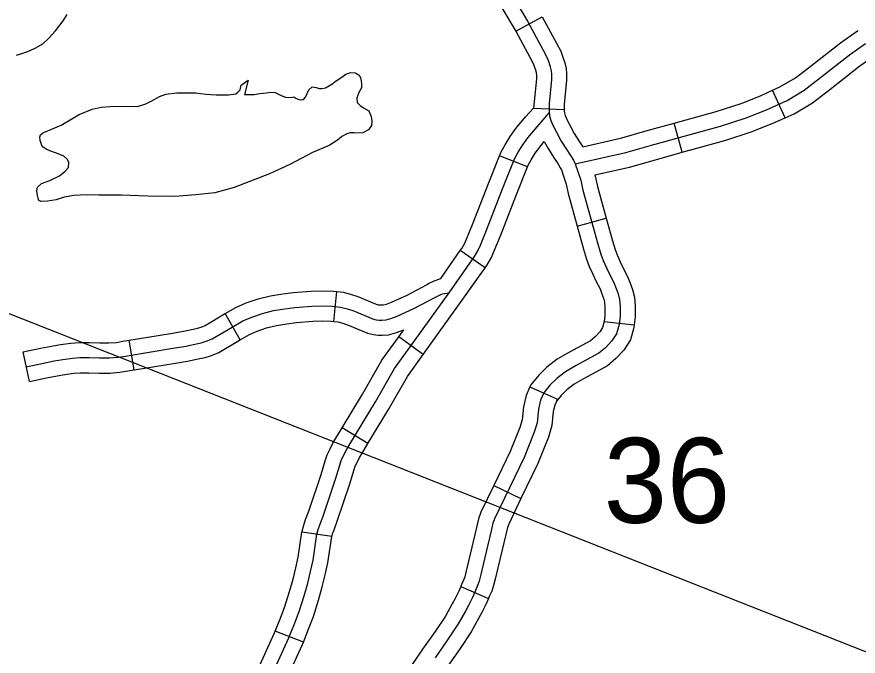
# Model space of a CAD drawing. Extents: x -3711 to 825, y -151 to 1050.
# Drawn here: x -2656.41 to -2609.55, y 277.96 to 313.59 of the extents above; entities that cross this region are included whole.
import ezdxf

# ---------------------------------------------------------------- set-up
doc = ezdxf.new("R2010")
doc.units = 0
for name, color, linetype in [('Level 32', 7, 'Continuous'), ('Level 35', 7, 'Continuous'), ('Level 5', 7, 'Continuous'), ('R_Dimension', 7, 'Continuous')]:
    doc.layers.add(name, color=color, linetype=linetype)

msp = doc.modelspace()

# ---------------------------------------------------------------- linework, layer by layer
at = {"layer": 'Level 32'}
for p, q in [((-2628.618, 312.787), (-2627.143, 313.594)), ((-2613.618, 307.967), (-2614.316, 309.497)), ((-2627.637, 308.51), (-2625.926, 308.429)), ((-2619.345, 306.045), (-2619.794, 307.665)), ((-2627.959, 305.224), (-2629.519, 305.85)), ((-2625.202, 301.927), (-2623.581, 302.374)), ((-2630.333, 299.602), (-2631.708, 300.57)), ((-2638.759, 296.615), (-2638.58, 298.287)), ((-2643.97, 295.593), (-2644.804, 297.053)), ((-2623.689, 296.614), (-2622.018, 296.428)), ((-2633.77, 294.775), (-2635.136, 295.756)), ((-2649.881, 293.91), (-2650.156, 295.569)), ((-2655.706, 293.269), (-2656.053, 294.915)), ((-2627.829, 292.973), (-2626.298, 292.278)), ((-2636.854, 289.808), (-2638.293, 290.678)), ((-2629.843, 287.474), (-2628.329, 286.743)), ((-2638.862, 284.622), (-2640.526, 284.867)), ((-2631.682, 281.844), (-2630.14, 281.174)), ((-2640.449, 278.744), (-2642.015, 279.357))]:
    msp.add_line(p, q, dxfattribs=at)
for points in [[(-2630.523, 318.676), (-2630.523, 318.262), (-2630.505, 317.663), (-2630.469, 316.962), (-2630.411, 316.498), (-2630.332, 316.081), (-2630.231, 315.716), (-2630.063, 315.233), (-2629.745, 314.657), (-2629.331, 314.001), (-2628.701, 312.938), (-2628.618, 312.787)], [(-2628.614, 314.44), (-2627.97, 313.355), (-2627.089, 311.743), (-2626.885, 311.336), (-2626.784, 311.064), (-2626.699, 310.81), (-2626.648, 310.589), (-2626.631, 310.386), (-2626.631, 310.097), (-2626.767, 308.757), (-2626.767, 308.401), (-2626.756, 308.241), (-2626.733, 308.079), (-2626.665, 307.807), (-2626.546, 307.553), (-2626.36, 307.163), (-2626.089, 306.671), (-2625.817, 306.23), (-2625.58, 305.873), (-2625.411, 305.602), (-2625.303, 305.395), (-2625.156, 304.974), (-2625.004, 304.482), (-2624.885, 303.94), (-2624.037, 300.869), (-2623.885, 300.36), (-2623.749, 300.004), (-2623.563, 299.597), (-2623.408, 299.25), (-2623.154, 298.779), (-2623.03, 298.452), (-2622.922, 298.156), (-2622.843, 297.831), (-2622.81, 297.456), (-2622.81, 296.912), (-2622.863, 296.439), (-2623.009, 295.933), (-2623.263, 295.535), (-2623.625, 295.154), (-2623.987, 294.846), (-2625.255, 294.157), (-2625.843, 293.815), (-2626.337, 293.436), (-2626.716, 293.056), (-2627.057, 292.638), (-2627.247, 292.221), (-2627.361, 291.727), (-2627.437, 290.968), (-2627.589, 290.436), (-2628.158, 289.031), (-2629.789, 285.652)], [(-2627.143, 313.594), (-2626.344, 312.133), (-2626.114, 311.672), (-2625.991, 311.345), (-2625.889, 311.038), (-2625.815, 310.719), (-2625.79, 310.421), (-2625.79, 310.055), (-2625.926, 308.715), (-2625.926, 308.429), (-2625.919, 308.329), (-2625.907, 308.241), (-2625.869, 308.089), (-2625.807, 307.956)], [(-2628.618, 312.787), (-2627.834, 311.353), (-2627.657, 311), (-2627.576, 310.784), (-2627.509, 310.582), (-2627.481, 310.459), (-2627.472, 310.351), (-2627.472, 310.14), (-2627.637, 308.51)], [(-2614.316, 309.497), (-2613.904, 309.685), (-2613.038, 310.201), (-2612.155, 310.874), (-2610.531, 312.153), (-2609.596, 312.812), (-2609.549, 312.839)], [(-2625.303, 305.395), (-2622.496, 306.037), (-2621.066, 306.44), (-2617.219, 307.508), (-2615.789, 307.972), (-2614.661, 308.415), (-2613.513, 308.939), (-2612.566, 309.504), (-2611.64, 310.209), (-2610.028, 311.479), (-2609.142, 312.104)], [(-2613.618, 307.967), (-2613.122, 308.194), (-2612.095, 308.806), (-2611.125, 309.545), (-2609.526, 310.805), (-2608.688, 311.395), (-2608.706, 311.385)], [(-2619.794, 307.665), (-2617.461, 308.313), (-2616.073, 308.763), (-2614.99, 309.189), (-2614.316, 309.497)], [(-2629.519, 305.85), (-2629.433, 306.064), (-2629.219, 306.466), (-2628.932, 306.928), (-2628.615, 307.373), (-2628.071, 308.011), (-2627.637, 308.51)], [(-2642.298, 276.691), (-2641.275, 278.939), (-2640.95, 279.771), (-2640.68, 280.457), (-2640.41, 281.323), (-2640.208, 282.031), (-2640.051, 282.683), (-2639.905, 283.313), (-2639.691, 284.763), (-2639.624, 285.022), (-2639.532, 285.288), (-2639.354, 285.764), (-2638.658, 287.821), (-2638.422, 288.608), (-2638.343, 288.867), (-2638.208, 289.137), (-2638.062, 289.429), (-2637.916, 289.676), (-2636.433, 292.127), (-2635.366, 293.994), (-2632.338, 298.213), (-2630.917, 300.233), (-2630.726, 300.56), (-2630.591, 300.874), (-2630.254, 301.706), (-2629.356, 304), (-2628.67, 305.709), (-2628.49, 306.046), (-2628.232, 306.462), (-2627.951, 306.856), (-2627.434, 307.463), (-2626.756, 308.241)], [(-2625.807, 307.956), (-2625.786, 307.912), (-2625.612, 307.547), (-2625.362, 307.094), (-2625.109, 306.683), (-2624.889, 306.352)], [(-2619.345, 306.045), (-2616.977, 306.703), (-2615.505, 307.18), (-2614.332, 307.641), (-2613.618, 307.967)], [(-2624.889, 306.352), (-2622.704, 306.851), (-2621.293, 307.249), (-2619.794, 307.665)], [(-2627.959, 305.224), (-2627.907, 305.354), (-2627.762, 305.626), (-2627.532, 305.996), (-2627.288, 306.338), (-2627.031, 306.639)], [(-2627.031, 306.639), (-2626.815, 306.247), (-2626.525, 305.776), (-2626.286, 305.418), (-2626.141, 305.184), (-2626.076, 305.061), (-2625.955, 304.712), (-2625.817, 304.268), (-2625.701, 303.738), (-2625.202, 301.927)], [(-2624.209, 304.783), (-2622.288, 305.222), (-2620.84, 305.63), (-2619.345, 306.045)], [(-2631.708, 300.57), (-2631.625, 300.689), (-2631.478, 300.939), (-2631.367, 301.198), (-2631.035, 302.017), (-2630.137, 304.31), (-2629.519, 305.85)], [(-2630.333, 299.602), (-2630.209, 299.778), (-2629.974, 300.18), (-2629.815, 300.551), (-2629.473, 301.395), (-2628.574, 303.69), (-2627.959, 305.224)], [(-2624.209, 304.783), (-2624.069, 304.141), (-2623.581, 302.374)], [(-2623.581, 302.374), (-2623.23, 301.102), (-2623.088, 300.631), (-2622.974, 300.329), (-2622.797, 299.943), (-2622.653, 299.621), (-2622.388, 299.129), (-2622.243, 298.746), (-2622.116, 298.401), (-2622.011, 297.967), (-2621.97, 297.492), (-2621.97, 296.866), (-2622.018, 296.428)], [(-2625.202, 301.927), (-2624.845, 300.637), (-2624.681, 300.09), (-2624.525, 299.679), (-2624.329, 299.25), (-2624.163, 298.879), (-2623.921, 298.429), (-2623.818, 298.159), (-2623.728, 297.912), (-2623.675, 297.694), (-2623.651, 297.419), (-2623.651, 296.959), (-2623.689, 296.614)], [(-2632.802, 299.015), (-2631.708, 300.57)], [(-2633.77, 294.775), (-2631.653, 297.726), (-2630.333, 299.602)], [(-2633.556, 298.683), (-2633.481, 298.723), (-2633.169, 298.879), (-2632.802, 299.015)], [(-2638.58, 298.287), (-2638.22, 298.248), (-2637.762, 298.123), (-2637.407, 298.005), (-2636.484, 297.621), (-2636.34, 297.561), (-2636.258, 297.54), (-2636.191, 297.534), (-2636.112, 297.534), (-2635.978, 297.543), (-2635.828, 297.581), (-2635.545, 297.689), (-2634.665, 298.089), (-2633.556, 298.683)], [(-2655.879, 294.092), (-2654.917, 294.295), (-2654.326, 294.413), (-2653.854, 294.497), (-2653.314, 294.565), (-2652.892, 294.599), (-2652.386, 294.599), (-2651.795, 294.582), (-2651.255, 294.582), (-2650.765, 294.616), (-2650.36, 294.683), (-2647.71, 295.122), (-2646.968, 295.241), (-2646.58, 295.325), (-2646.141, 295.426), (-2645.854, 295.511), (-2645.533, 295.646), (-2644.419, 296.305), (-2643.828, 296.642), (-2643.322, 296.862), (-2642.731, 297.065), (-2642.107, 297.217), (-2641.482, 297.318), (-2640.925, 297.386), (-2639.98, 297.47), (-2639.373, 297.487), (-2638.849, 297.47), (-2638.377, 297.419), (-2638.006, 297.318), (-2637.702, 297.217), (-2636.807, 296.845), (-2636.605, 296.761), (-2636.402, 296.71), (-2636.233, 296.693), (-2636.082, 296.693), (-2635.845, 296.71), (-2635.575, 296.778), (-2635.221, 296.913), (-2634.292, 297.335), (-2633.094, 297.977), (-2632.834, 298.107), (-2632.706, 298.154), (-2632.588, 298.182), (-2632.46, 298.201), (-2632.338, 298.213)], [(-2644.804, 297.053), (-2644.205, 297.395), (-2643.626, 297.646), (-2642.968, 297.872), (-2642.274, 298.041), (-2641.6, 298.151), (-2641.014, 298.222), (-2640.029, 298.31), (-2639.371, 298.328), (-2638.791, 298.309), (-2638.58, 298.287)], [(-2650.156, 295.569), (-2647.845, 295.952), (-2647.123, 296.067), (-2646.763, 296.145), (-2646.354, 296.24), (-2646.137, 296.304), (-2645.912, 296.398), (-2644.842, 297.031), (-2644.804, 297.053)], [(-2643.97, 295.593), (-2643.451, 295.89), (-2643.018, 296.078), (-2642.495, 296.257), (-2641.94, 296.392), (-2641.364, 296.486), (-2640.837, 296.55), (-2639.931, 296.631), (-2639.375, 296.646), (-2638.908, 296.631), (-2638.759, 296.615)], [(-2638.759, 296.615), (-2638.533, 296.591), (-2638.249, 296.513), (-2637.996, 296.429), (-2637.13, 296.069), (-2636.87, 295.961), (-2636.547, 295.88), (-2636.275, 295.853), (-2636.052, 295.853), (-2635.712, 295.877), (-2635.323, 295.974), (-2634.85, 296.154)], [(-2635.136, 295.756), (-2634.85, 296.154)], [(-2623.689, 296.614), (-2623.69, 296.604), (-2623.783, 296.283), (-2623.928, 296.055), (-2624.204, 295.766), (-2624.466, 295.543), (-2625.667, 294.89), (-2626.313, 294.515), (-2626.893, 294.069), (-2627.34, 293.621), (-2627.777, 293.086), (-2627.828, 292.974)], [(-2622.018, 296.428), (-2622.035, 296.275), (-2622.236, 295.584), (-2622.598, 295.014), (-2623.047, 294.542), (-2623.509, 294.149), (-2624.843, 293.424), (-2625.374, 293.116), (-2625.781, 292.803), (-2626.092, 292.492), (-2626.337, 292.191), (-2626.298, 292.278)], [(-2638.293, 290.678), (-2637.158, 292.554), (-2636.074, 294.449), (-2635.136, 295.756)], [(-2656.053, 294.915), (-2655.086, 295.118), (-2654.483, 295.239), (-2653.98, 295.329), (-2653.4, 295.401), (-2652.925, 295.439), (-2652.373, 295.439), (-2651.783, 295.422), (-2651.284, 295.422), (-2650.864, 295.451), (-2650.498, 295.512), (-2650.156, 295.569)], [(-2649.881, 293.91), (-2647.576, 294.293), (-2646.812, 294.414), (-2646.396, 294.505), (-2645.927, 294.613), (-2645.571, 294.718), (-2645.154, 294.893), (-2643.997, 295.578), (-2643.97, 295.593)], [(-2636.854, 289.808), (-2635.709, 291.701), (-2634.658, 293.539), (-2633.77, 294.775)], [(-2655.706, 293.269), (-2654.748, 293.471), (-2654.17, 293.587), (-2653.728, 293.666), (-2653.228, 293.729), (-2652.858, 293.758), (-2652.398, 293.758), (-2651.807, 293.741), (-2651.226, 293.741), (-2650.667, 293.78), (-2650.222, 293.854), (-2649.881, 293.91)], [(-2627.829, 292.973), (-2628.047, 292.492), (-2628.192, 291.864), (-2628.266, 291.126), (-2628.385, 290.71), (-2628.927, 289.372), (-2629.843, 287.474)], [(-2626.298, 292.278), (-2626.447, 291.95), (-2626.53, 291.59), (-2626.608, 290.809), (-2626.793, 290.162), (-2627.389, 288.691), (-2628.329, 286.743)], [(-2640.526, 284.867), (-2640.516, 284.931), (-2640.429, 285.266), (-2640.323, 285.572), (-2640.146, 286.046), (-2639.459, 288.077), (-2639.227, 288.851), (-2639.127, 289.179), (-2638.96, 289.512), (-2638.801, 289.831), (-2638.638, 290.108), (-2638.293, 290.678)], [(-2638.866, 284.596), (-2638.819, 284.778), (-2638.741, 285.003), (-2638.562, 285.482), (-2637.857, 287.566), (-2637.617, 288.365), (-2637.56, 288.555), (-2637.456, 288.761), (-2637.323, 289.027), (-2637.195, 289.245), (-2636.854, 289.808)], [(-2629.843, 287.474), (-2630.564, 285.981), (-2630.699, 285.614), (-2630.813, 285.138), (-2631.258, 283.253), (-2631.374, 282.721), (-2631.465, 282.389), (-2631.531, 282.191), (-2631.635, 281.952), (-2631.682, 281.844)], [(-2628.329, 286.743), (-2629.014, 285.324), (-2629.087, 285.126), (-2629.177, 284.749), (-2629.619, 282.88), (-2629.741, 282.32), (-2629.855, 281.902), (-2629.96, 281.588), (-2630.094, 281.281), (-2630.14, 281.174)], [(-2629.789, 285.652), (-2629.893, 285.37), (-2629.995, 284.943), (-2630.438, 283.067), (-2630.558, 282.521), (-2630.66, 282.145), (-2630.745, 281.89), (-2630.865, 281.617), (-2631.035, 281.224), (-2631.257, 280.781), (-2631.427, 280.474), (-2631.819, 279.757), (-2632.416, 278.87), (-2633.115, 277.864)], [(-2642.015, 279.357), (-2641.732, 280.079), (-2641.473, 280.736), (-2641.216, 281.563), (-2641.021, 282.245), (-2640.869, 282.877), (-2640.731, 283.469), (-2640.526, 284.867)], [(-2640.449, 278.744), (-2640.167, 279.464), (-2639.886, 280.178), (-2639.605, 281.083), (-2639.395, 281.817), (-2639.233, 282.49), (-2639.078, 283.157), (-2638.862, 284.622)], [(-2631.682, 281.844), (-2631.797, 281.58), (-2632.001, 281.173), (-2632.163, 280.879), (-2632.538, 280.194), (-2633.11, 279.344), (-2633.806, 278.342), (-2634.743, 276.982)], [(-2630.14, 281.174), (-2630.273, 280.869), (-2630.513, 280.389), (-2630.691, 280.068), (-2631.1, 279.32), (-2631.722, 278.396), (-2632.423, 277.385), (-2633.358, 276.029)], [(-2644.446, 273.986), (-2644.299, 274.338), (-2643.976, 275.121), (-2643.06, 277.046), (-2642.05, 279.267), (-2642.015, 279.357)], [(-2642.896, 273.335), (-2642.746, 273.693), (-2642.439, 274.439), (-2641.536, 276.336), (-2640.501, 278.612), (-2640.449, 278.744)]]:
    msp.add_lwpolyline(points, dxfattribs=at)
at = {"layer": 'Level 35'}
for points in [[(-2656.431, 311.449), (-2656.121, 311.547), (-2655.791, 311.663), (-2655.383, 311.838), (-2654.956, 312.091), (-2654.645, 312.382), (-2654.257, 312.81), (-2653.829, 313.373), (-2653.596, 313.723)], [(-2654.865, 307.16), (-2653.942, 307.564), (-2652.942, 308.141), (-2652.212, 308.449), (-2651.712, 308.565), (-2651.212, 308.603), (-2650.423, 308.622), (-2649.693, 308.603), (-2649.231, 308.738), (-2648.847, 308.93), (-2648.462, 309.161), (-2648.116, 309.277), (-2647.501, 309.354), (-2646.443, 309.354), (-2646.174, 309.315), (-2645.866, 309.277), (-2645.308, 309.238), (-2644.905, 309.238), (-2644.616, 309.238), (-2644.212, 309.296), (-2644.097, 309.392), (-2643.962, 309.527), (-2643.924, 309.719), (-2643.905, 309.777), (-2643.789, 309.873), (-2643.52, 310.066), (-2643.732, 309.257), (-2643.193, 309.257), (-2642.866, 309.315), (-2642.501, 309.354), (-2642.27, 309.392), (-2642.02, 309.373), (-2641.867, 309.296), (-2641.694, 309.2), (-2641.444, 309.123), (-2641.117, 309.103), (-2640.982, 309.142), (-2640.867, 309.065), (-2640.751, 309.007), (-2640.617, 308.969), (-2640.444, 308.988), (-2640.328, 309.123), (-2640.232, 309.315), (-2640.136, 309.527), (-2639.963, 309.7), (-2639.732, 309.661), (-2639.578, 309.604), (-2639.425, 309.604), (-2639.213, 309.642), (-2638.867, 309.835), (-2638.617, 310.027), (-2638.309, 310.239), (-2638.079, 310.393), (-2637.809, 310.489), (-2637.54, 310.47), (-2637.386, 310.354), (-2637.271, 310.219), (-2637.232, 310.027), (-2637.213, 309.835), (-2637.213, 309.642), (-2637.367, 309.373), (-2637.463, 309.065), (-2637.444, 308.815), (-2637.29, 308.642), (-2637.098, 308.526), (-2636.809, 308.353), (-2636.675, 308.045), (-2636.636, 307.776), (-2636.656, 307.545), (-2636.829, 307.295), (-2637.136, 307.121), (-2637.521, 307.102), (-2637.617, 307.121), (-2637.848, 307.121), (-2638.021, 307.064), (-2638.309, 306.929), (-2638.463, 306.794), (-2638.598, 306.679), (-2639.021, 306.429), (-2639.944, 306.025), (-2641.194, 305.37), (-2642.328, 304.851), (-2644.309, 304.081), (-2645.385, 303.792), (-2646.443, 303.677), (-2647.616, 303.581)], [(-2647.616, 303.581), (-2649.116, 303.6), (-2650.577, 303.658), (-2651.846, 303.658), (-2652.519, 303.677), (-2653.231, 303.638), (-2653.769, 303.542), (-2654.211, 303.388), (-2654.692, 303.311), (-2655.057, 303.292), (-2655.173, 303.35), (-2655.211, 303.485), (-2655.25, 303.638), (-2655.288, 303.889), (-2655.25, 304.1), (-2655.038, 304.312), (-2654.577, 304.466), (-2654.038, 304.735), (-2653.711, 304.985), (-2653.538, 305.197), (-2653.519, 305.486), (-2653.596, 305.659), (-2653.788, 305.832), (-2654.192, 305.986), (-2654.48, 306.082), (-2654.769, 306.217), (-2654.942, 306.332), (-2655.019, 306.429), (-2655.115, 306.698), (-2655.134, 306.89), (-2655.096, 307.025), (-2654.98, 307.102), (-2654.865, 307.16)]]:
    msp.add_lwpolyline(points, dxfattribs=at)
at = {"layer": 'R_Dimension'}
msp.add_line((-2469.437, 223.07), (-2866.636, 379.848), dxfattribs=at)

# ---------------------------------------------------------------- texts
at = {"layer": 'Level 5'}
msp.add_text('36', height=4.7343, dxfattribs=at).set_placement((-2623.721, 285.392))

doc.saveas('drawing.dxf')
